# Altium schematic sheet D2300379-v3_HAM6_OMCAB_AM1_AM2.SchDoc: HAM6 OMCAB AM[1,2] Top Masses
size C; Engineer: L. Sanchez; Organization: LIGO Laboratory; Address1: California Institute of Technology; Address2: Massachusetts Institute of Technology; DocumentNumber: D2300379; Revision: v2; SheetNumber: 5; SheetTotal: 9
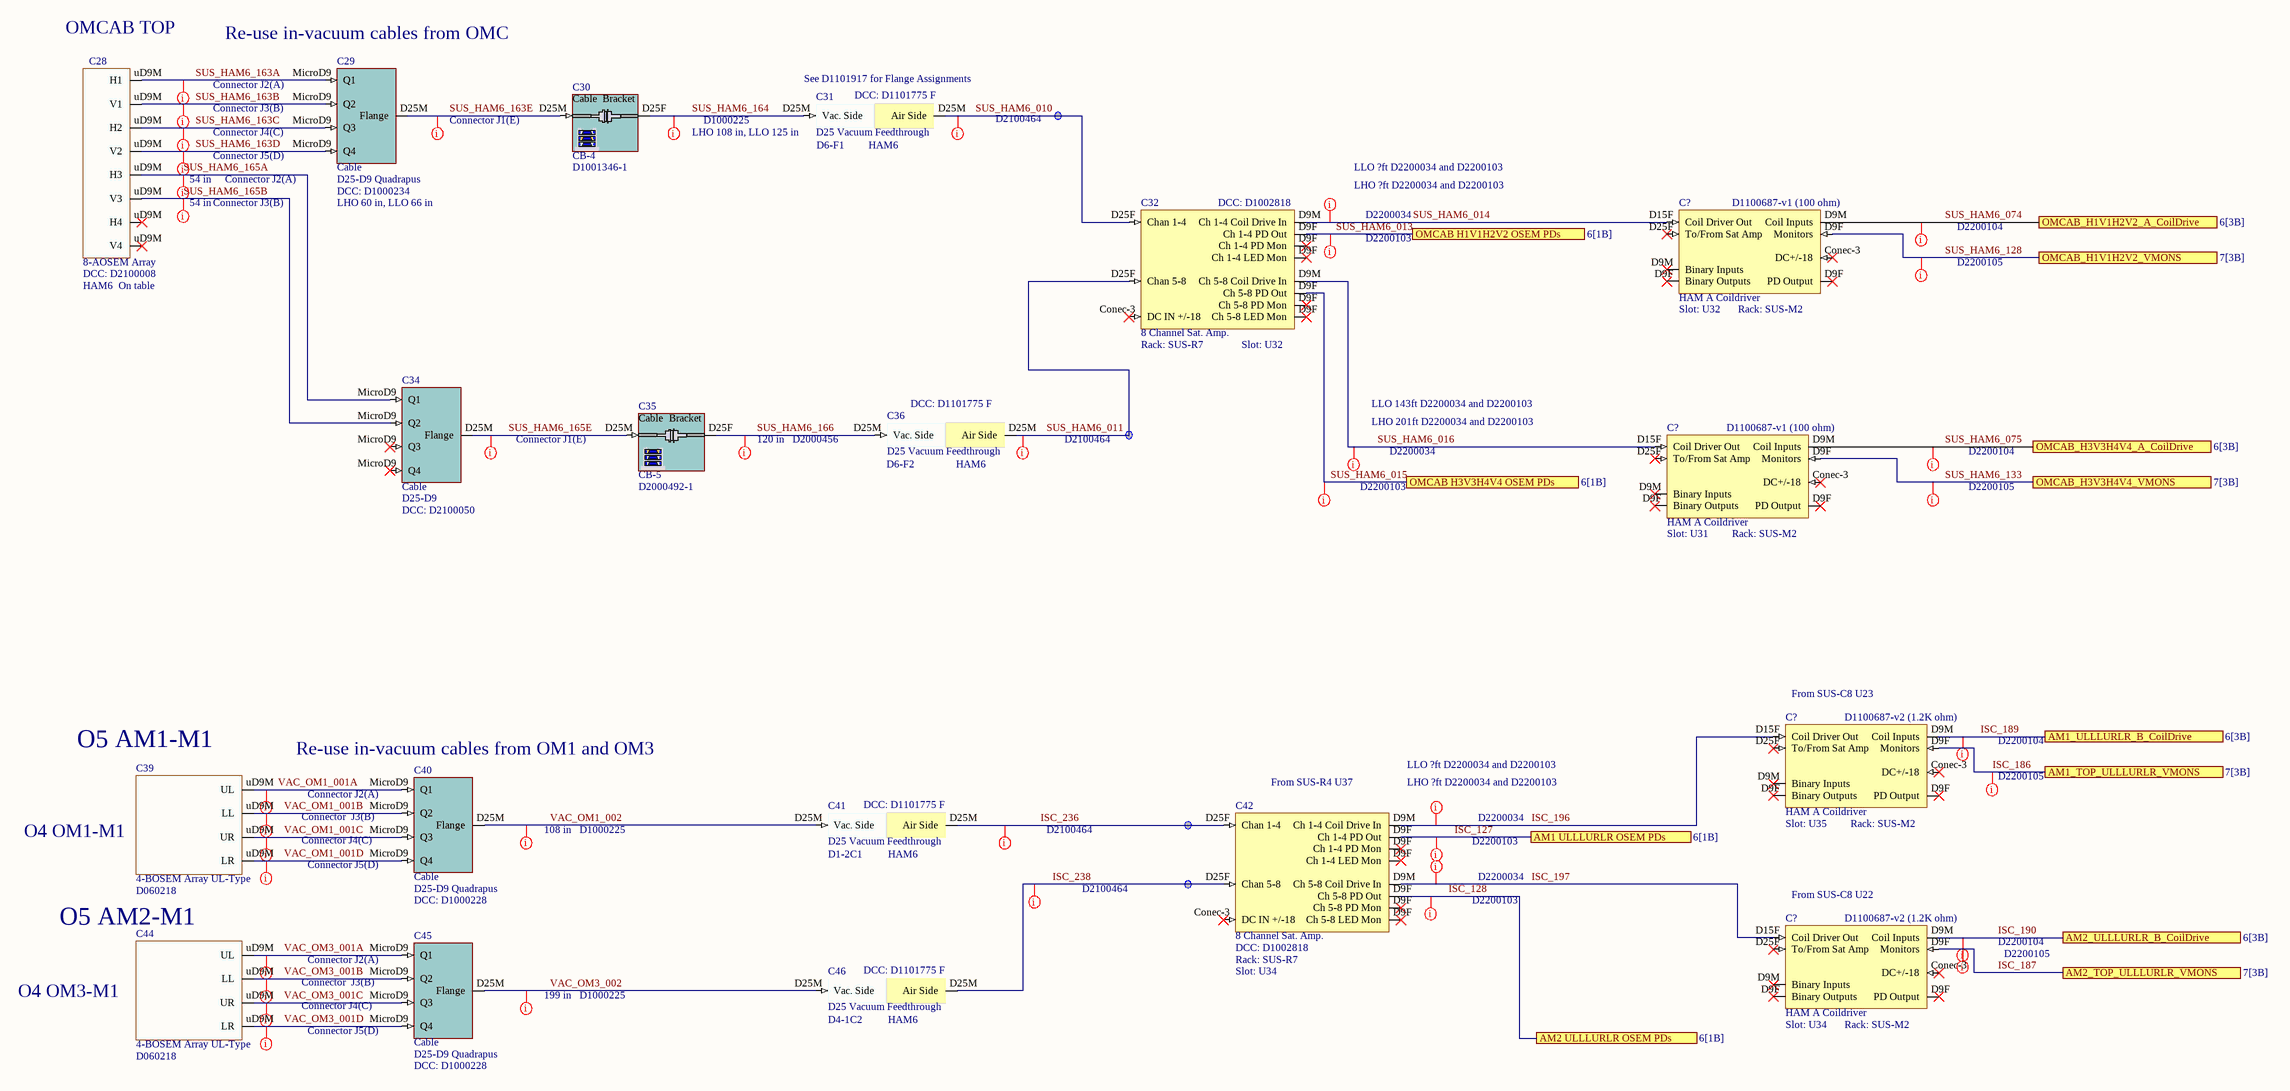
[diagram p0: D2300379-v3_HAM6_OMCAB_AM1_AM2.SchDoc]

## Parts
(Parts that share a designator on the sheet are numbered #1, #2 ... from top to bottom, then left to right.)
C28  8-AOSEM Array  DCC: D2100008  Rack: HAM6  Slot: On table
C29  Cable  value D25-D9 Quadrapus  DCC: D1000234
C30  Rack: CB-4  DCC: D1001346-1  (hidden comment: D1001346-3 2nd Cable Bracket)
C31  D25 Vacuum Feedthrough  DCC: D1101775 F  Feedthrough: D6-F1  Chamber: HAM6
C32  8 Channel Sat. Amp.  DCC: D1002818  Rack: SUS-R7  Slot: U32
C34  Cable  value D25-D9  DCC: D2100050
C35  Rack: CB-5  DCC: D2000492-1  (hidden comment: D1001346-3 3rd Cable Bracket)
C36  D25 Vacuum Feedthrough  DCC: D1101775 F  Feedthrough: D6-F2  Chamber: HAM6
C39  4-BOSEM Array UL-Type  DCC: D060218
C40  Cable  value D25-D9 Quadrapus  DCC: D1000228
C41  D25 Vacuum Feedthrough  DCC: D1101775 F  Feedthrough: D1-2C1  Chamber: HAM6
C42  8 Channel Sat. Amp.  DCC: D1002818  Rack: SUS-R7  Slot: U34
C44  4-BOSEM Array UL-Type  DCC: D060218
C45  Cable  value D25-D9 Quadrapus  DCC: D1000228
C46  D25 Vacuum Feedthrough  DCC: D1101775 F  Feedthrough: D4-1C2  Chamber: HAM6
C?#1  HAM A Coildriver  Rack: SUS-M2  Slot: U32
C?#2  HAM A Coildriver  Rack: SUS-M2  Slot: U31
C?#3  HAM A Coildriver  Rack: SUS-M2  Slot: U35
C?#4  HAM A Coildriver  Rack: SUS-M2  Slot: U34

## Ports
AM1 ULLLURLR OSEM PDs (see 6[1B]), AM1_TOP_ULLLURLR_VMONS (see 7[3B]), AM1_ULLLURLR_B_CoilDrive (see 6[3B]), AM2 ULLLURLR OSEM PDs (see 6[1B]), AM2_TOP_ULLLURLR_VMONS (see 7[3B]), AM2_ULLLURLR_B_CoilDrive (see 6[3B]), OMCAB H1V1H2V2 OSEM PDs (see 6[1B]), OMCAB H3V3H4V4 OSEM PDs (see 6[1B]), OMCAB_H1V1H2V2_A_CoilDrive (see 6[3B]), OMCAB_H1V1H2V2_VMONS (see 7[3B]), OMCAB_H3V3H4V4_A_CoilDrive (see 6[3B]), OMCAB_H3V3H4V4_VMONS (see 7[3B])

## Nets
ISC_127: C42.D9F(Ch_1-4_PD_Out) ; port AM1 ULLLURLR OSEM PDs
ISC_128: C42.D9F(Ch_5-8_PD_Out) ; port AM2 ULLLURLR OSEM PDs
ISC_186: C?#3.D9F(PD_Output) ; port AM1_TOP_ULLLURLR_VMONS
ISC_187: C?#4.D9F(PD_Output) ; port AM2_TOP_ULLLURLR_VMONS
ISC_189: C?#3.D9M(Coil_Inputs) ; port AM1_ULLLURLR_B_CoilDrive
ISC_190: C?#4.D9M(Coil_Inputs) ; port AM2_ULLLURLR_B_CoilDrive
ISC_196: C42.D9M(Ch_1-4_Coil_Drive_In) C?#3.D15F(Coil_Driver_Out)
ISC_197: C42.D9M(Ch_5-8_Coil_Drive_In) C?#4.D15F(Coil_Driver_Out)
ISC_236: C41.D25M(Air_Side) C42.D25F(Chan_1-4)
ISC_238: C42.D25F(Chan_5-8) C46.D25M(Air_Side)
SUS_HAM6_010: C31.D25M(Air_Side) C32.D25F(Chan_1-4)
SUS_HAM6_011: C32.D25F(Chan_5-8) C36.D25M(Air_Side)
SUS_HAM6_013: C32.D9F(Ch_1-4_PD_Out) ; port OMCAB H1V1H2V2 OSEM PDs
SUS_HAM6_014: C32.D9M(Ch_1-4_Coil_Drive_In) C?#1.D15F(Coil_Driver_Out)
SUS_HAM6_015: C32.D9F(Ch_5-8_PD_Out) ; port OMCAB H3V3H4V4 OSEM PDs
SUS_HAM6_016: C32.D9M(Ch_5-8_Coil_Drive_In) C?#2.D15F(Coil_Driver_Out)
SUS_HAM6_074: C?#1.D9M(Coil_Inputs) ; port OMCAB_H1V1H2V2_A_CoilDrive
SUS_HAM6_075: C?#2.D9M(Coil_Inputs) ; port OMCAB_H3V3H4V4_A_CoilDrive
SUS_HAM6_128: C?#1.D9F(PD_Output) ; port OMCAB_H1V1H2V2_VMONS
SUS_HAM6_133: C?#2.D9F(PD_Output) ; port OMCAB_H3V3H4V4_VMONS
SUS_HAM6_163A: C28.uD9M(H1) C29.MicroD9(Q1)
SUS_HAM6_163B: C28.uD9M(V1) C29.MicroD9(Q2)
SUS_HAM6_163C: C28.uD9M(H2) C29.MicroD9(Q3)
SUS_HAM6_163D: C28.uD9M(V2) C29.MicroD9(Q4)
SUS_HAM6_163E: C29.D25M(Flange) C30.D25M
SUS_HAM6_164: C30.D25F C31.D25M(Vac._Side)
SUS_HAM6_165A: C28.uD9M(H3) C34.MicroD9(Q1)
SUS_HAM6_165B: C28.uD9M(V3) C34.MicroD9(Q2)
SUS_HAM6_165E: C34.D25M(Flange) C35.D25M
SUS_HAM6_166: C35.D25F C36.D25M(Vac._Side)
VAC_OM1_001A: C39.uD9M(UL) C40.MicroD9(Q1)
VAC_OM1_001B: C39.uD9M(LL) C40.MicroD9(Q2)
VAC_OM1_001C: C39.uD9M(UR) C40.MicroD9(Q3)
VAC_OM1_001D: C39.uD9M(LR) C40.MicroD9(Q4)
VAC_OM1_002: C40.D25M(Flange) C41.D25M(Vac._Side)
VAC_OM3_001A: C44.uD9M(UL) C45.MicroD9(Q1)
VAC_OM3_001B: C44.uD9M(LL) C45.MicroD9(Q2)
VAC_OM3_001C: C44.uD9M(UR) C45.MicroD9(Q3)
VAC_OM3_001D: C44.uD9M(LR) C45.MicroD9(Q4)
VAC_OM3_002: C45.D25M(Flange) C46.D25M(Vac._Side)

Not connected (* = marked no-connect by the designer): C32 Conec-3(DC_IN_+/-18)*; C42 Conec-3(DC_IN_+/-18)*; C?#1 Conec-3(DC+/-18)* D25F(To/From_Sat_Amp)*; C?#2 Conec-3(DC+/-18)* D25F(To/From_Sat_Amp)*; C?#3 Conec-3(DC+/-18)* D25F(To/From_Sat_Amp)*; C?#4 Conec-3(DC+/-18)* D25F(To/From_Sat_Amp)*

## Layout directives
Length: 6.5ft; DCC: Connector J1(E): SUS_HAM6_163E, SUS_HAM6_165E
DCC: D2100464: ISC_236, ISC_238, SUS_HAM6_010, SUS_HAM6_011
DCC: Connector J2(A): SUS_HAM6_163A, SUS_HAM6_165A, VAC_OM1_001A, VAC_OM3_001A
DCC: Connector J3(B): SUS_HAM6_163B, SUS_HAM6_165B
DCC: D1000225: SUS_HAM6_164, VAC_OM1_002, VAC_OM3_002
DCC: Connector J4(C): SUS_HAM6_163C, VAC_OM1_001C, VAC_OM3_001C
DCC: Connector J5(D): SUS_HAM6_163D, VAC_OM1_001D, VAC_OM3_001D
DCC: D2200105: ISC_186, ISC_187, SUS_HAM6_128, SUS_HAM6_133
DCC: D2200104: ISC_189, ISC_190, SUS_HAM6_074, SUS_HAM6_075
DCC: D2200034: ISC_196, ISC_197, SUS_HAM6_014, SUS_HAM6_016
DCC: D2200103: ISC_127, ISC_128, SUS_HAM6_013, SUS_HAM6_015
DCC: D2000456: SUS_HAM6_166
DCC: Connector  J3(B): VAC_OM1_001B, VAC_OM3_001B

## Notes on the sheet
- (near C28) OMCAB TOP
- (near C29) Re-use in-vacuum cables from OMC
- (near C31) See D1101917 for Flange Assignments
- (near C31) LHO 108 in, LLO 125 in
- 54 in
- LHO 60 in, LLO 66 in
- LLO ?ft D2200034 and D2200103
- LHO ?ft D2200034 and D2200103
- (near C?#1) D1100687-v1 (100 ohm)
- 120 in
- LLO 143ft D2200034 and D2200103
- LHO 201ft D2200034 and D2200103
- (near C?#2) D1100687-v1 (100 ohm)
- O5 AM1-M1
- (near C40) Re-use in-vacuum cables from OM1 and OM3
- (near C?#3) From SUS-C8 U23
- (near C?#3) D1100687-v2 (1.2K ohm)
- (near C42) From SUS-R4 U37
- (near C42) LHO ?ft D2200034 and D2200103
- O4 OM1-M1
- 108 in
- O5 AM2-M1
- (near C?#4) From SUS-C8 U22
- (near C?#4) D1100687-v2 (1.2K ohm)
- O4 OM3-M1
- 199 in

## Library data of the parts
C28 = AOSEM_BHSS_M1: BHSS Suspended Platform AOSEM Array
C29 C34 C40 C45 = Flange: Rack: SUS-R?; Serial: Sxxxxxxx; Slot: U?; System: SUS
C30 = D1001346-3 2nd Cable Bracket: D1001346-3 2nd Cable Bracket  for HAM Tables; Serial: Sxxxxxxx; System: SUS
C31 C36 C41 C46 = VacFeedD25: Serial: Sxxxxxxx; System: ISC; Rack: R?; Slot: U?
C32 C42 = 8 Channel Sat. Amp.: Serial: Sxxxxxxx; System: ISC
C35 = D1001346-3 3rd Cable Bracket: D1001346-3 3rd Cable Bracket for HAM Tables; Serial: Sxxxxxxx; System: SUS
C39 C44 = 4-BOSEM Array UL-Type: Rack: R?; Slot: U?; Serial: Sxxxxxxx; System: SUS
C?#1-C?#4 = CD HAM-A D1100687: Serial: Sxxxxxxx; System: ISC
